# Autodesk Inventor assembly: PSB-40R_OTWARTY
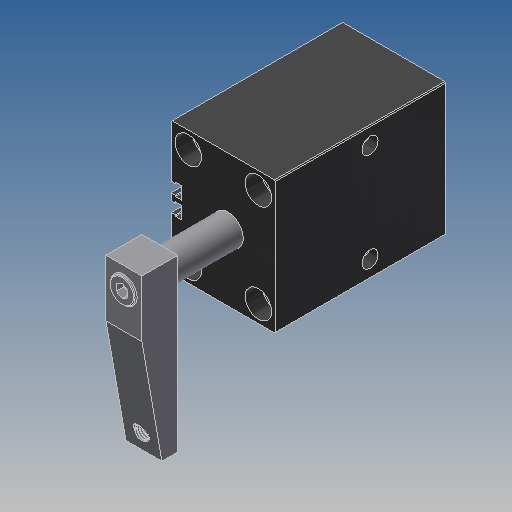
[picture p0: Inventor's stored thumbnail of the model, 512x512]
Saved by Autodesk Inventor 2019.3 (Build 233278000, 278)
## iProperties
Company: Î¢ÈíÖÐ¹ú
Created: 2013-10
Part Number: PSB-40R_OTWARTY
Material: Ogólny
Description: STEP AP203
Document SubType Name: Assembly
Designer: CADENGINEERING4
Sending System: SolidWorks 2012
Preprocessor: SwSTEP 2.0
Title: PSB-40.STEP
Author: Î¢ÈíÓÃ»§
Revision Number: ÈÎºÎ
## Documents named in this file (6)
- E:\SERWER_ZAPAS\Pneumatic\PSB PNEUMATIC SWING\PSB-40\PSB-40R_OTWARTY.iam
- E:\SERWER_ZAPAS\Pneumatic\PSB PNEUMATIC SWING\PSB-40\PSB40BT.ipt
- E:\SERWER_ZAPAS\Pneumatic\PSB PNEUMATIC SWING\PSB-40\PSB40HSG.ipt
- E:\SERWER_ZAPAS\Pneumatic\PSB PNEUMATIC SWING\PSB-40\PSB40YB.ipt
- E:\SERWER_ZAPAS\Pneumatic\PSB PNEUMATIC SWING\PSB-40\PSB40HG.ipt
- E:\SERWER_ZAPAS\Pneumatic\PSB PNEUMATIC SWING\PSB-40\socket head cap screw_iso_ISO 4762 M8 x 25 --- 25S.ipt
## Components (5 placed, 5 different names)
1. PSB40BT_1 — Zestawiające:1, Kątowe:1, Zestawiające:7
2. PSB40HSG_2 — Zestawiające:1, Zestawiające:3, Zestawiające:4, Zestawiające:7
3. PSB40YB_3 — Zestawiające:3, Zestawiające:4, Zestawiające:5, Zestawiające:6, Kątowe:1
4. PSB40HG_4
5. socket head cap screw_iso_ISO 4762 M8 x 25 --- 25S_5 — Zestawiające:5, Zestawiające:6
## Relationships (7: Mate 6, Angle 1)
- Zestawiające:1 [Mate]: PSB40BT_1 ↔ PSB40HSG_2
- Zestawiające:3 [Mate]: PSB40HSG_2 ↔ PSB40YB_3
- Zestawiające:4 [Mate]: PSB40HSG_2 ↔ PSB40YB_3
- Zestawiające:5 [Mate]: PSB40YB_3 ↔ socket head cap screw_iso_ISO 4762 M8 x 25 --- 25S_5
- Zestawiające:6 [Mate]: PSB40YB_3 ↔ socket head cap screw_iso_ISO 4762 M8 x 25 --- 25S_5
- Kątowe:1 [Angle]: PSB40BT_1 ↔ PSB40YB_3
- Zestawiające:7 [Mate]: PSB40BT_1 ↔ PSB40HSG_2
